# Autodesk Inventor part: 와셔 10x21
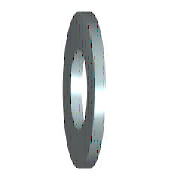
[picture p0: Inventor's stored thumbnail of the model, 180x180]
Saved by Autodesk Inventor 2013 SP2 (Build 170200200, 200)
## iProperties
Created: 2012-02
Part Number: 와셔 10x21
Material: 강철, 연강
Description: 평면 와셔
Document SubType Name: Modeling
Standard: KS B 1326
Designer: mduedu
Standards Organization: KS
Language: ko-KR
Size Designation: 10x21
Categories: <MemberInstance><Categories><Category DisplayName="조임쇠" InternalName="e4da775c-781d-43d5-af7c-5136215cf5a6" Mnemonic="FSTN"><Category DisplayName="와셔" InternalN
Density: 1 g/cm^3
IsCustomPart: 1
Author: mduedu
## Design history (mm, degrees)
sketch "스케치"
  geometry: C1 r 10.5 at (0, 0); C2 r 5.25 at (0, 0); 1 further point
  constraints: 2 centre point, 2 coincident
  dimensions: "d0" = 10.5 diameter of C2 (= SD1); "d1" = 21 diameter of C1 (= SD2)
extrude "본체" new body sketch "스케치" distance "d2" = 2 (= SD); taper "d3" = 0 deg
workaxis "Work Axis1"
workplane "Work Plane1"
body "Solid1"
other parameters: "SD1" = 10.5 [user parameter; used in 1 equation term], "SD2" = 21 [user parameter; used in 1 equation term], "SD" = 2 [user parameter; used in 1 equation term], "d4" = 0, "d5" = 0, "d6" = 0, "d7" = 0
